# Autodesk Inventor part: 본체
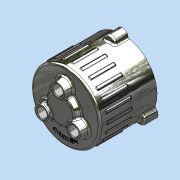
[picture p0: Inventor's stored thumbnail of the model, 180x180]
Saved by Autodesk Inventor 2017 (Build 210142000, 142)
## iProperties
Created: 2015-11
Part Number: 본체
Document SubType Name: 모델링
Designer: mdu
Material: 알루미늄 6061
Density: 2.7 g/cm^3
Mass: 676.615 g
Surface Area: 733.607 cm^2
Volume: 250.598 cm^3
Appearance: 알루미늄 - 평지
변환 표준: STEP AP214IS
파일 이름: C:\Users\SeoGD\Desktop\?쒗뿕\紐몄껜.stp
전처리기: Build: 253, Release: 2010 SP1 - Date: Wed 07/29/2009
전송 단위: 밀리미터
불확실성: 0.01
Author: mdu
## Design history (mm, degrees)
sketch "스케치2"
  geometry: C1 r 52 at (0, 0); 1 further point
  constraints: 1 centre point, 1 coincident
  dimensions: "d9" = 104 diameter of C1
extrude "돌출2" new body sketch "스케치2" distance "d10" = 85.5; taper "d11" = 0 deg
feature "쉘1" dims "d12" = 7
sketch "스케치3" dims "d13" = 55
  geometry: C1 r 7.5 at (0, 27.5); C2 r 12.5 at (0, 27.5); 2 further points
  constraints: 2 centre point, 2 coincident, 2 vertical alignment, 2 other
  dimensions: "d14" = 15 diameter of C1; "d15" = 25 diameter of C2
extrude "돌출3" join sketch "스케치3" distance "d16" = 12; taper "d17" = -10 deg
sketch "스케치4"
  geometry: L1 (0, 0)-(0, 93.5); L2 (0, 71.5)-(12.624, 71.5); L3 (-45, 78.5)-(45, 78.5) reference; L4 (-52, 85.5)-(52, 85.5) reference; L5 (12.624, 71.5)-(14.5, 78.5); L6 (20.381, 93.5)-(0, 93.5); L7 (25, 85.5)-(14.5, 78.5); L8 (25, 85.5)-(20.381, 93.5)
  constraints: 12 end point, 3 point on line, 1 perpendicular, 1 vertical
  dimensions: "d35" = 105 deg angle of L5 L3; "d36" = 7 distance between parallel lines of L2 L3; "d37" = 8 distance between parallel lines of L6 L4; "d51" = 29 diameter of L5.end L1; "d92" = 50 diameter of L7.start L1; "d93" = 120 deg angle of L6 L8
revolve "회전1" sketch "스케치4" stored, may be unused: angle "d38" = 90 deg
hole "구멍2" diameter "d20" = 15; stored, may be unused: countersink angle "d24" = 90 deg, drill point angle "d26" = 118 deg; dims "d18" = 10, "d19" = 10, "d21" = 6, "d22" = 4, "d23" = 2, "d25" = 15
chamfer "모따기1" distance "d27" = 1; stored, may be unused: second distance "d28" = 2, angle "d29" = 45 deg
hole "구멍3" diameter "d41" = 15; stored, may be unused: countersink angle "d45" = 90 deg, drill point angle "d47" = 0 deg; dims "d42" = 6, "d43" = 22, "d44" = 13, "d46" = 16, "d96" = 10, "d97" = 10
chamfer "모따기2" distance "d48" = 1; stored, may be unused: second distance "d49" = 2, angle "d50" = 45 deg
fillet "모깎기1" dims "d52" = 3
fillet "모깎기2" dims "d53" = 3, "d72" = 0.2, "d94" = 2
sketch "스케치5"
  geometry: A1 r 52 centre (0, 0) between (52, 0) and (-8.472, 51.305) reference; A2 r 8.5 centre (0, 52) between (8.472, 51.305) and (-8.472, 51.305); 1 further point
  constraints: 5 point on circle, 1 centre point, 1 horizontal alignment
  dimensions: "d54" = 90 deg dimension on point (0, 0) A2.centre A1.start; "d55" = 52 distance of A2.centre point (0, 0); "d56" = 17 diameter of A2
extrude "돌출4" join sketch "스케치5" distance "d57" = 20; taper "d58" = 0 deg
fillet "모깎기3" dims "d59" = 3
hole "구멍4" diameter "d62" = 4.134; stored, may be unused: countersink angle "d66" = 90 deg, drill point angle "d68" = 118 deg; dims "d60" = 10, "d61" = 10, "d63" = 12, "d64" = 22, "d65" = 13, "d67" = 15
sketch "스케치6"
  geometry: C1 r 49 at (0, 0) reference; C2 r 42.5 at (0, 0); 1 further point
  constraints: 1 centre point, 1 coincident, 1 other
  dimensions: "d73" = 85 diameter of C2
feature "엠보싱1" sketch "스케치6" dims "d74" = 0.5, "d75" = 0
node "작업 평면1"
sketch "스케치7"
  geometry: A1 r 52 centre (0, 0) between (4.478, 51.807) and (-4.478, 51.807) reference; A2 r 3 centre (0, 50) between (2.28, 51.95) and (-2.28, 51.95); 1 further point
  constraints: 4 point on circle, 1 centre point, 1 vertical alignment
  dimensions: "d77" = 3 radius of A2; "d91" = 50 distance of point (0, 0) A2.centre
extrude "돌출5" join sketch "스케치7" distance "d79" = 38; taper "d80" = 0 deg
fillet "모깎기4" dims "d81" = 1
fillet "모깎기5" dims "d82" = 1
node "솔리드1"
node "솔리드 본체"
node "곡면 본체"
pattern_circular "원형 패턴1" dims angle "d31" = 360 deg
pattern_circular "원형 패턴2" dims angle "d70" = 360 deg
pattern_circular "원형 패턴3" dims angle "d84" = 360 deg
node "솔리드2"
